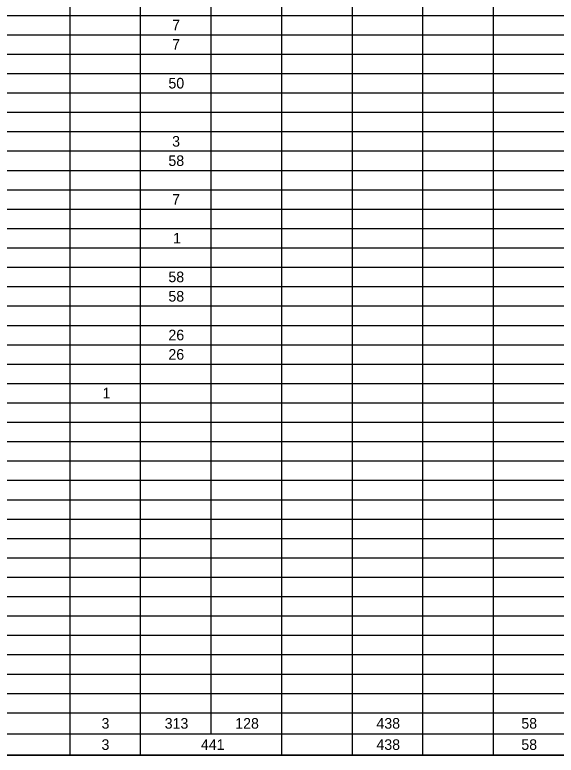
# Model space of a CAD drawing. Extents: x 91011267 to 91022583, y 37007614 to 37014266.
# Drawn here: x 91011662 to 91012046, y 37007614 to 37008139 of the extents above; entities that cross this region are included whole.
import ezdxf

# ---------------------------------------------------------------- set-up
doc = ezdxf.new("R2010")
doc.units = 0
doc.layers.add('SC_Scratch2', color=7, linetype='Continuous')
doc.layers.add('SH_Data', color=7, linetype='Continuous')

msp = doc.modelspace()

# ---------------------------------------------------------------- linework, layer by layer
at = {"layer": 'SC_Scratch2'}
msp.add_lwpolyline([(91011277.35, 37008663.81), (91012802.35, 37008663.81), (91012802.35, 37007613.81), (91011277.35, 37007613.81)], close=True, dxfattribs=at)
at = {"layer": 'SH_Data'}
for p, q in [((91011700.45, 37008289.61), (91011700.45, 37008083.53)), ((91011750.54, 37008289.61), (91011750.54, 37008083.53)), ((91011800.62, 37008289.61), (91011800.62, 37008083.53)), ((91011850.71, 37008289.61), (91011850.71, 37008083.53)), ((91011900.79, 37008289.61), (91011900.79, 37008083.53)), ((91011950.88, 37008289.61), (91011950.88, 37008083.53)), ((91012000.97, 37008289.61), (91012000.97, 37008083.53)), ((91011650.36, 37008138.48), (91011950.88, 37008138.48)), ((91011950.88, 37008138.48), (91012000.97, 37008138.48)), ((91012000.97, 37008138.48), (91012551.92, 37008138.48)), ((91011650.36, 37008124.75), (91011950.88, 37008124.75)), ((91011950.88, 37008124.75), (91012000.97, 37008124.75)), ((91012000.97, 37008124.75), (91012551.92, 37008124.75)), ((91011650.36, 37008111.01), (91011950.88, 37008111.01)), ((91011950.88, 37008111.01), (91012000.97, 37008111.01)), ((91012000.97, 37008111.01), (91012551.92, 37008111.01)), ((91011650.36, 37008097.27), (91011950.88, 37008097.27)), ((91011950.88, 37008097.27), (91012000.97, 37008097.27)), ((91012000.97, 37008097.27), (91012551.92, 37008097.27)), ((91011650.36, 37008083.53), (91011950.88, 37008083.53)), ((91011700.45, 37008083.53), (91011700.45, 37008069.79)), ((91011750.54, 37008083.53), (91011750.54, 37008069.79)), ((91011800.62, 37008083.53), (91011800.62, 37008069.79)), ((91011850.71, 37008083.53), (91011850.71, 37008069.79)), ((91011900.79, 37008083.53), (91011900.79, 37008069.79)), ((91011950.88, 37008083.53), (91012000.97, 37008083.53)), ((91011950.88, 37008083.53), (91011950.88, 37008069.79)), ((91012000.97, 37008083.53), (91012551.92, 37008083.53)), ((91012000.97, 37008083.53), (91012000.97, 37008069.79)), ((91011650.36, 37008069.79), (91011950.88, 37008069.79)), ((91011700.45, 37008069.79), (91011700.45, 37008056.05)), ((91011750.54, 37008069.79), (91011750.54, 37008056.05)), ((91011800.62, 37008069.79), (91011800.62, 37008056.05)), ((91011850.71, 37008069.79), (91011850.71, 37008056.05)), ((91011900.79, 37008069.79), (91011900.79, 37008056.05)), ((91011950.88, 37008069.79), (91012000.97, 37008069.79)), ((91011950.88, 37008069.79), (91011950.88, 37008056.05)), ((91012000.97, 37008069.79), (91012551.92, 37008069.79)), ((91012000.97, 37008069.79), (91012000.97, 37008056.05)), ((91011650.36, 37008056.05), (91011950.88, 37008056.05)), ((91011700.45, 37008056.05), (91011700.45, 37008014.84)), ((91011750.54, 37008056.05), (91011750.54, 37008014.84)), ((91011800.62, 37008056.05), (91011800.62, 37008014.84)), ((91011850.71, 37008056.05), (91011850.71, 37008014.84)), ((91011900.79, 37008056.05), (91011900.79, 37008014.84)), ((91011950.88, 37008056.05), (91012000.97, 37008056.05)), ((91011950.88, 37008056.05), (91011950.88, 37008014.84)), ((91012000.97, 37008056.05), (91012551.92, 37008056.05)), ((91012000.97, 37008056.05), (91012000.97, 37008014.84)), ((91011650.36, 37008042.32), (91011950.88, 37008042.32)), ((91011950.88, 37008042.32), (91012000.97, 37008042.32)), ((91012000.97, 37008042.32), (91012551.92, 37008042.32)), ((91011650.36, 37008028.58), (91011950.88, 37008028.58)), ((91011950.88, 37008028.58), (91012000.97, 37008028.58)), ((91012000.97, 37008028.58), (91012551.92, 37008028.58)), ((91011650.36, 37008014.84), (91011950.88, 37008014.84)), ((91011700.45, 37008014.84), (91011700.45, 37008001.1)), ((91011750.54, 37008014.84), (91011750.54, 37008001.1)), ((91011800.62, 37008014.84), (91011800.62, 37008001.1)), ((91011850.71, 37008014.84), (91011850.71, 37008001.1)), ((91011900.79, 37008014.84), (91011900.79, 37008001.1)), ((91011950.88, 37008014.84), (91012000.97, 37008014.84)), ((91011950.88, 37008014.84), (91011950.88, 37008001.1)), ((91012000.97, 37008014.84), (91012551.92, 37008014.84)), ((91012000.97, 37008014.84), (91012000.97, 37008001.1)), ((91011650.36, 37008001.1), (91011950.88, 37008001.1)), ((91011700.45, 37008001.1), (91011700.45, 37007987.36)), ((91011750.54, 37008001.1), (91011750.54, 37007987.36)), ((91011800.62, 37008001.1), (91011800.62, 37007987.36)), ((91011850.71, 37008001.1), (91011850.71, 37007987.36)), ((91011900.79, 37008001.1), (91011900.79, 37007987.36)), ((91011950.88, 37008001.1), (91012000.97, 37008001.1)), ((91011950.88, 37008001.1), (91011950.88, 37007987.36)), ((91012000.97, 37008001.1), (91012551.92, 37008001.1)), ((91012000.97, 37008001.1), (91012000.97, 37007987.36)), ((91011650.36, 37007987.36), (91011950.88, 37007987.36)), ((91011700.45, 37007987.36), (91011700.45, 37007946.15)), ((91011750.54, 37007987.36), (91011750.54, 37007946.15)), ((91011800.62, 37007987.36), (91011800.62, 37007946.15)), ((91011850.71, 37007987.36), (91011850.71, 37007946.15)), ((91011900.79, 37007987.36), (91011900.79, 37007946.15)), ((91011950.88, 37007987.36), (91012000.97, 37007987.36)), ((91011950.88, 37007987.36), (91011950.88, 37007946.15)), ((91012000.97, 37007987.36), (91012551.92, 37007987.36)), ((91012000.97, 37007987.36), (91012000.97, 37007946.15)), ((91011650.36, 37007973.62), (91011950.88, 37007973.62)), ((91011950.88, 37007973.62), (91012000.97, 37007973.62)), ((91012000.97, 37007973.62), (91012551.92, 37007973.62)), ((91011650.36, 37007959.89), (91011950.88, 37007959.89)), ((91011950.88, 37007959.89), (91012000.97, 37007959.89)), ((91012000.97, 37007959.89), (91012551.92, 37007959.89)), ((91011650.36, 37007946.15), (91011950.88, 37007946.15)), ((91011700.45, 37007946.15), (91011700.45, 37007932.41)), ((91011750.54, 37007946.15), (91011750.54, 37007932.41)), ((91011800.62, 37007946.15), (91011800.62, 37007932.41)), ((91011850.71, 37007946.15), (91011850.71, 37007932.41)), ((91011900.79, 37007946.15), (91011900.79, 37007932.41)), ((91011950.88, 37007946.15), (91012000.97, 37007946.15)), ((91011950.88, 37007946.15), (91011950.88, 37007932.41)), ((91012000.97, 37007946.15), (91012551.92, 37007946.15)), ((91012000.97, 37007946.15), (91012000.97, 37007932.41)), ((91011650.36, 37007932.41), (91011950.88, 37007932.41)), ((91011700.45, 37007932.41), (91011700.45, 37007918.67)), ((91011750.54, 37007932.41), (91011750.54, 37007918.67)), ((91011800.62, 37007932.41), (91011800.62, 37007918.67)), ((91011850.71, 37007932.41), (91011850.71, 37007918.67)), ((91011900.79, 37007932.41), (91011900.79, 37007918.67)), ((91011950.88, 37007932.41), (91012000.97, 37007932.41)), ((91011950.88, 37007932.41), (91011950.88, 37007918.67)), ((91012000.97, 37007932.41), (91012551.92, 37007932.41)), ((91012000.97, 37007932.41), (91012000.97, 37007918.67)), ((91011650.36, 37007918.67), (91011950.88, 37007918.67)), ((91011700.45, 37007918.67), (91011700.45, 37007613.81)), ((91011750.54, 37007918.67), (91011750.54, 37007613.81)), ((91011800.62, 37007918.67), (91011800.62, 37007628.86)), ((91011850.71, 37007918.67), (91011850.71, 37007613.81)), ((91011900.79, 37007918.67), (91011900.79, 37007613.81)), ((91011950.88, 37007918.67), (91012000.97, 37007918.67)), ((91011950.88, 37007918.67), (91011950.88, 37007613.81)), ((91012000.97, 37007918.67), (91012551.92, 37007918.67)), ((91012000.97, 37007918.67), (91012000.97, 37007613.81)), ((91011650.36, 37007904.93), (91011950.88, 37007904.93)), ((91011950.88, 37007904.93), (91012000.97, 37007904.93)), ((91012000.97, 37007904.93), (91012551.92, 37007904.93)), ((91011650.36, 37007891.19), (91011950.88, 37007891.19)), ((91011950.88, 37007891.19), (91012000.97, 37007891.19)), ((91012000.97, 37007891.19), (91012551.92, 37007891.19)), ((91011650.36, 37007877.46), (91011950.88, 37007877.46)), ((91011950.88, 37007877.46), (91012000.97, 37007877.46)), ((91012000.97, 37007877.46), (91012551.92, 37007877.46)), ((91011650.36, 37007863.72), (91011950.88, 37007863.72)), ((91011950.88, 37007863.72), (91012000.97, 37007863.72)), ((91012000.97, 37007863.72), (91012551.92, 37007863.72)), ((91011650.36, 37007849.98), (91011950.88, 37007849.98)), ((91011950.88, 37007849.98), (91012000.97, 37007849.98)), ((91012000.97, 37007849.98), (91012551.92, 37007849.98)), ((91011650.36, 37007836.24), (91011950.88, 37007836.24)), ((91011950.88, 37007836.24), (91012000.97, 37007836.24)), ((91012000.97, 37007836.24), (91012551.92, 37007836.24)), ((91011650.36, 37007822.5), (91011950.88, 37007822.5)), ((91011950.88, 37007822.5), (91012000.97, 37007822.5)), ((91012000.97, 37007822.5), (91012551.92, 37007822.5)), ((91011650.36, 37007808.76), (91011950.88, 37007808.76)), ((91011950.88, 37007808.76), (91012000.97, 37007808.76)), ((91012000.97, 37007808.76), (91012551.92, 37007808.76)), ((91011650.36, 37007795.03), (91011950.88, 37007795.03)), ((91011950.88, 37007795.03), (91012000.97, 37007795.03)), ((91012000.97, 37007795.03), (91012551.92, 37007795.03)), ((91011650.36, 37007781.29), (91011950.88, 37007781.29)), ((91011950.88, 37007781.29), (91012000.97, 37007781.29)), ((91012000.97, 37007781.29), (91012551.92, 37007781.29)), ((91011650.36, 37007767.55), (91011950.88, 37007767.55)), ((91011950.88, 37007767.55), (91012000.97, 37007767.55)), ((91012000.97, 37007767.55), (91012551.92, 37007767.55)), ((91011650.36, 37007753.81), (91011950.88, 37007753.81)), ((91011950.88, 37007753.81), (91012000.97, 37007753.81)), ((91012000.97, 37007753.81), (91012551.92, 37007753.81)), ((91011650.36, 37007740.07), (91011950.88, 37007740.07)), ((91011950.88, 37007740.07), (91012000.97, 37007740.07)), ((91012000.97, 37007740.07), (91012551.92, 37007740.07)), ((91011650.36, 37007726.33), (91011950.88, 37007726.33)), ((91011950.88, 37007726.33), (91012000.97, 37007726.33)), ((91012000.97, 37007726.33), (91012551.92, 37007726.33)), ((91011650.36, 37007712.6), (91011950.88, 37007712.6)), ((91011950.88, 37007712.6), (91012000.97, 37007712.6)), ((91012000.97, 37007712.6), (91012551.92, 37007712.6)), ((91011650.36, 37007698.86), (91011950.88, 37007698.86)), ((91011950.88, 37007698.86), (91012000.97, 37007698.86)), ((91012000.97, 37007698.86), (91012551.92, 37007698.86)), ((91011650.36, 37007685.12), (91011950.88, 37007685.12)), ((91011950.88, 37007685.12), (91012000.97, 37007685.12)), ((91012000.97, 37007685.12), (91012551.92, 37007685.12)), ((91011650.36, 37007671.38), (91011950.88, 37007671.38)), ((91011950.88, 37007671.38), (91012000.97, 37007671.38)), ((91012000.97, 37007671.38), (91012551.92, 37007671.38)), ((91011650.36, 37007657.64), (91011950.88, 37007657.64)), ((91011950.88, 37007657.64), (91012000.97, 37007657.64)), ((91012000.97, 37007657.64), (91012551.92, 37007657.64)), ((91011650.36, 37007643.9), (91011950.88, 37007643.9)), ((91011950.88, 37007643.9), (91012000.97, 37007643.9)), ((91012000.97, 37007643.9), (91012551.92, 37007643.9)), ((91011650.36, 37007628.86), (91011950.88, 37007628.86)), ((91011950.88, 37007628.86), (91012000.97, 37007628.86)), ((91012000.97, 37007628.86), (91012551.92, 37007628.86)), ((91011650.36, 37007613.81), (91011950.88, 37007613.81)), ((91011950.88, 37007613.81), (91012000.97, 37007613.81)), ((91012000.97, 37007613.81), (91012551.92, 37007613.81))]:
    msp.add_line(p, q, dxfattribs=at)

# ---------------------------------------------------------------- texts
for s, height, p in [('7', 7.52, (91011773.15, 37008127.85)), ('7', 7.52, (91011773.15, 37008114.12)), ('50', 7.523, (91011770.51, 37008086.64)), ('3', 7.52, (91011773.15, 37008045.42)), ('58', 7.523, (91011770.49, 37008031.69)), ('7', 7.52, (91011773.15, 37008004.21)), ('1', 7.52, (91011773.81, 37007976.73)), ('58', 7.523, (91011770.49, 37007949.26)), ('58', 7.523, (91011770.49, 37007935.52)), ('26', 7.523, (91011770.5, 37007908.04)), ('26', 7.523, (91011770.5, 37007894.3)), ('1', 7.52, (91011723.72, 37007866.83)), ('3', 7.52, (91011723.06, 37007632.62)), ('313', 7.523, (91011767.85, 37007632.62)), ('128', 7.523, (91011817.93, 37007632.62)), ('438', 7.523, (91011918.1, 37007632.62)), ('58', 7.523, (91012020.92, 37007632.62)), ('3', 7.52, (91011723.06, 37007617.57)), ('441', 7.523, (91011793.55, 37007617.57)), ('438', 7.523, (91011918.1, 37007617.57)), ('58', 7.523, (91012020.92, 37007617.57))]:
    msp.add_text(s, height=height, dxfattribs=at).set_placement(p)

doc.saveas('drawing.dxf')
